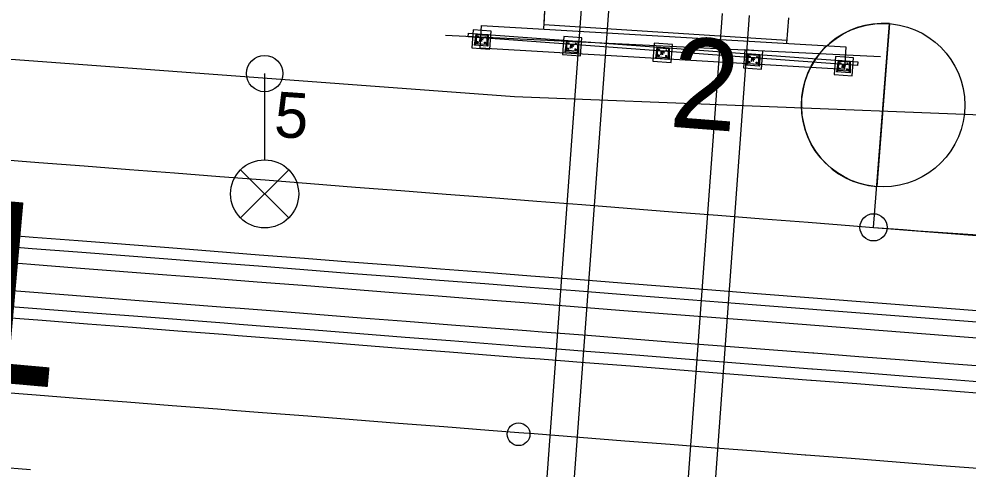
# Model space of a CAD drawing. Extents: x -670359 to -668019, y -978807 to -976674.
# Drawn here: x -669486.95 to -669466.04, y -977146.25 to -977136.34 of the extents above; entities that cross this region are included whole.
import ezdxf

# ---------------------------------------------------------------- set-up
doc = ezdxf.new("R2010")
doc.units = 0
for name, color, linetype in [('SO 01-20-01', 7, 'Continuous'), ('SO 01-20-01_Demolice', 7, 'Continuous'), ('SO 01-86-01', 7, 'Continuous'), ('SO 11-10-01', 7, 'Continuous'), ('SO 11-12-01', 7, 'Continuous'), ('ŽBP', 7, 'Continuous')]:
    doc.layers.add(name, color=color, linetype=linetype)

# ---------------------------------------------------------------- blocks, each defined once
blk = doc.blocks.new('POINT_DISPLAY')
blk.add_line((0, 0), (0, 0))

msp = doc.modelspace()

# ---------------------------------------------------------------- linework, layer by layer
at = {"layer": 'SO 01-20-01'}
for p, q in [((-669475.385, -977136.563), (-669475.124, -977131.902)), ((-669475.38, -977136.467), (-669475.124, -977131.902)), ((-669475.576, -977150.04), (-669474.546, -977136.022)), ((-669474.959, -977149.839), (-669473.947, -977136.066)), ((-669472.47, -977150.083), (-669471.452, -977136.221)), ((-669471.836, -977149.643), (-669470.854, -977136.265)), ((-669469.998, -977136.315), (-669470.039, -977136.876)), ((-669470.034, -977136.814), (-669475.38, -977136.467)), ((-669476.885, -977136.673), (-669476.918, -977136.916)), ((-669476.871, -977136.689), (-669476.886, -977136.889)), ((-669476.615, -977136.693), (-669476.885, -977136.673)), ((-669476.871, -977136.689), (-669476.885, -977136.673)), ((-669476.631, -977136.707), (-669476.871, -977136.689)), ((-669476.854, -977136.731), (-669476.814, -977136.734)), ((-669476.835, -977136.752), (-669476.832, -977136.712)), ((-669476.795, -977136.755), (-669476.801, -977136.835)), ((-669476.716, -977136.761), (-669476.795, -977136.755)), ((-669476.756, -977136.758), (-669476.761, -977136.838)), ((-669476.694, -977136.742), (-669476.654, -977136.745)), ((-669476.676, -977136.764), (-669476.673, -977136.724)), ((-669476.631, -977136.707), (-669476.646, -977136.906)), ((-669476.631, -977136.707), (-669476.615, -977136.693)), ((-669476.615, -977136.693), (-669476.618, -977136.938)), ((-669476.886, -977136.889), (-669476.918, -977136.916)), ((-669476.618, -977136.938), (-669476.918, -977136.916)), ((-669476.646, -977136.906), (-669476.886, -977136.889)), ((-669476.863, -977136.85), (-669476.823, -977136.853)), ((-669476.844, -977136.872), (-669476.841, -977136.832)), ((-669476.719, -977136.801), (-669476.798, -977136.795)), ((-669476.788, -977136.768), (-669476.793, -977136.827)), ((-669476.724, -977136.768), (-669476.783, -977136.764)), ((-669476.703, -977136.862), (-669476.663, -977136.865)), ((-669476.685, -977136.883), (-669476.682, -977136.843)), ((-669476.646, -977136.906), (-669476.618, -977136.938)), ((-669474.89, -977136.82), (-669474.923, -977137.063)), ((-669474.876, -977136.836), (-669474.891, -977137.035)), ((-669474.621, -977136.839), (-669474.89, -977136.82)), ((-669474.876, -977136.836), (-669474.89, -977136.82)), ((-669474.637, -977136.853), (-669474.876, -977136.836)), ((-669474.859, -977136.877), (-669474.819, -977136.88)), ((-669474.841, -977136.899), (-669474.838, -977136.859)), ((-669474.801, -977136.901), (-669474.807, -977136.981)), ((-669474.724, -977136.947), (-669474.804, -977136.941)), ((-669474.721, -977136.907), (-669474.801, -977136.901)), ((-669474.794, -977136.915), (-669474.798, -977136.974)), ((-669474.73, -977136.915), (-669474.788, -977136.91)), ((-669474.761, -977136.904), (-669474.767, -977136.984)), ((-669474.7, -977136.889), (-669474.66, -977136.892)), ((-669474.681, -977136.91), (-669474.678, -977136.87)), ((-669474.637, -977136.853), (-669474.652, -977137.053)), ((-669474.637, -977136.853), (-669474.621, -977136.839)), ((-669474.621, -977136.839), (-669474.624, -977137.085)), ((-669472.895, -977136.966), (-669472.928, -977137.209)), ((-669472.626, -977136.986), (-669472.895, -977136.966)), ((-669472.882, -977136.982), (-669472.895, -977136.966)), ((-669474.891, -977137.035), (-669474.923, -977137.063)), ((-669474.624, -977137.085), (-669474.923, -977137.063)), ((-669474.652, -977137.053), (-669474.891, -977137.035)), ((-669474.868, -977136.997), (-669474.828, -977137)), ((-669474.85, -977137.018), (-669474.847, -977136.978)), ((-669474.708, -977137.009), (-669474.669, -977137.011)), ((-669474.69, -977137.03), (-669474.687, -977136.99)), ((-669474.652, -977137.053), (-669474.624, -977137.085)), ((-669472.882, -977136.982), (-669472.896, -977137.182)), ((-669472.642, -977137), (-669472.882, -977136.982)), ((-669472.873, -977137.143), (-669472.833, -977137.146)), ((-669472.865, -977137.024), (-669472.825, -977137.027)), ((-669472.855, -977137.165), (-669472.852, -977137.125)), ((-669472.846, -977137.045), (-669472.843, -977137.005)), ((-669472.806, -977137.048), (-669472.812, -977137.128)), ((-669472.729, -977137.094), (-669472.809, -977137.088)), ((-669472.726, -977137.054), (-669472.806, -977137.048)), ((-669472.799, -977137.062), (-669472.804, -977137.12)), ((-669472.735, -977137.061), (-669472.794, -977137.057)), ((-669472.766, -977137.051), (-669472.772, -977137.131)), ((-669472.714, -977137.155), (-669472.674, -977137.158)), ((-669472.705, -977137.035), (-669472.665, -977137.038)), ((-669472.695, -977137.176), (-669472.692, -977137.137)), ((-669472.687, -977137.057), (-669472.684, -977137.017)), ((-669472.642, -977137), (-669472.657, -977137.199)), ((-669472.642, -977137), (-669472.626, -977136.986)), ((-669472.626, -977136.986), (-669472.629, -977137.231)), ((-669470.901, -977137.113), (-669470.934, -977137.356)), ((-669470.887, -977137.129), (-669470.902, -977137.328)), ((-669470.632, -977137.133), (-669470.901, -977137.113)), ((-669470.887, -977137.129), (-669470.901, -977137.113)), ((-669470.648, -977137.146), (-669470.887, -977137.129)), ((-669470.87, -977137.17), (-669470.83, -977137.173)), ((-669470.851, -977137.192), (-669470.849, -977137.152)), ((-669470.692, -977137.203), (-669470.689, -977137.163)), ((-669470.648, -977137.146), (-669470.662, -977137.346)), ((-669470.648, -977137.146), (-669470.632, -977137.133)), ((-669470.632, -977137.133), (-669470.635, -977137.378)), ((-669472.896, -977137.182), (-669472.928, -977137.209)), ((-669472.629, -977137.231), (-669472.928, -977137.209)), ((-669472.657, -977137.199), (-669472.896, -977137.182)), ((-669472.657, -977137.199), (-669472.629, -977137.231)), ((-669470.902, -977137.328), (-669470.934, -977137.356)), ((-669470.635, -977137.378), (-669470.934, -977137.356)), ((-669470.662, -977137.346), (-669470.902, -977137.328)), ((-669470.879, -977137.29), (-669470.839, -977137.293)), ((-669470.86, -977137.311), (-669470.857, -977137.271)), ((-669470.812, -977137.195), (-669470.817, -977137.274)), ((-669470.735, -977137.24), (-669470.815, -977137.234)), ((-669470.732, -977137.2), (-669470.812, -977137.195)), ((-669470.805, -977137.208), (-669470.809, -977137.267)), ((-669470.74, -977137.208), (-669470.799, -977137.203)), ((-669470.772, -977137.197), (-669470.778, -977137.277)), ((-669470.719, -977137.302), (-669470.679, -977137.305)), ((-669470.71, -977137.182), (-669470.67, -977137.185)), ((-669470.701, -977137.323), (-669470.698, -977137.283)), ((-669470.662, -977137.346), (-669470.635, -977137.378)), ((-669468.906, -977137.259), (-669468.939, -977137.503)), ((-669468.892, -977137.275), (-669468.907, -977137.475)), ((-669468.637, -977137.279), (-669468.906, -977137.259)), ((-669468.892, -977137.275), (-669468.906, -977137.259)), ((-669468.653, -977137.293), (-669468.892, -977137.275)), ((-669468.875, -977137.317), (-669468.835, -977137.32)), ((-669468.857, -977137.338), (-669468.854, -977137.298)), ((-669468.817, -977137.341), (-669468.823, -977137.421)), ((-669468.74, -977137.387), (-669468.82, -977137.381)), ((-669468.737, -977137.347), (-669468.817, -977137.341)), ((-669468.81, -977137.355), (-669468.814, -977137.413)), ((-669468.746, -977137.354), (-669468.805, -977137.35)), ((-669468.777, -977137.344), (-669468.783, -977137.424)), ((-669468.716, -977137.328), (-669468.676, -977137.331)), ((-669468.697, -977137.35), (-669468.694, -977137.31)), ((-669468.653, -977137.293), (-669468.668, -977137.492)), ((-669468.653, -977137.293), (-669468.637, -977137.279)), ((-669468.637, -977137.279), (-669468.64, -977137.525)), ((-669468.907, -977137.475), (-669468.939, -977137.503)), ((-669468.64, -977137.525), (-669468.939, -977137.503)), ((-669468.668, -977137.492), (-669468.907, -977137.475)), ((-669468.884, -977137.436), (-669468.844, -977137.439)), ((-669468.866, -977137.458), (-669468.863, -977137.418)), ((-669468.725, -977137.448), (-669468.685, -977137.451)), ((-669468.706, -977137.47), (-669468.703, -977137.43)), ((-669468.668, -977137.492), (-669468.64, -977137.525))]:
    msp.add_line(p, q, dxfattribs=at)
for points in [[(-669477.049, -977136.656), (-669468.472, -977137.286), (-669468.478, -977137.366), (-669477.055, -977136.736)], [(-669476.544, -977136.611), (-669476.943, -977136.581), (-669476.972, -977136.98), (-669476.574, -977137.01)], [(-669474.55, -977136.757), (-669474.949, -977136.728), (-669474.978, -977137.127), (-669474.579, -977137.156)], [(-669472.555, -977136.904), (-669472.954, -977136.874), (-669472.983, -977137.273), (-669472.584, -977137.303)], [(-669470.56, -977137.05), (-669470.959, -977137.021), (-669470.989, -977137.42), (-669470.59, -977137.449)], [(-669468.566, -977137.197), (-669468.965, -977137.168), (-669468.994, -977137.566), (-669468.595, -977137.596)]]:
    msp.add_lwpolyline(points, close=True, dxfattribs=at)
for centre in [(-669476.834, -977136.732), (-669476.674, -977136.744), (-669476.843, -977136.852), (-669476.683, -977136.863), (-669474.839, -977136.879), (-669474.68, -977136.89), (-669474.848, -977136.998), (-669474.688, -977137.01), (-669472.853, -977137.145), (-669472.845, -977137.025), (-669472.694, -977137.157), (-669472.685, -977137.037), (-669470.85, -977137.172), (-669470.69, -977137.183), (-669470.859, -977137.291), (-669470.699, -977137.303), (-669468.855, -977137.318), (-669468.696, -977137.33), (-669468.864, -977137.438), (-669468.705, -977137.45)]:
    msp.add_circle(centre, 0.01, dxfattribs=at)
for centre, radius, start, end in [((-669476.801, -977136.827), 0.008, 265.7861, 355.7984), ((-669476.783, -977136.769), 0.005, 85.7984, 175.7984), ((-669476.724, -977136.76), 0.008, 265.7861, 355.7984), ((-669474.789, -977136.915), 0.005, 85.7984, 175.7984), ((-669474.729, -977136.907), 0.008, 265.7861, 355.7984), ((-669474.806, -977136.973), 0.008, 265.7861, 355.7984), ((-669472.811, -977137.12), 0.008, 265.7861, 355.7984), ((-669472.794, -977137.062), 0.005, 85.7984, 175.7984), ((-669472.734, -977137.053), 0.008, 265.7861, 355.7984), ((-669470.817, -977137.266), 0.008, 265.7861, 355.7984), ((-669470.8, -977137.208), 0.005, 85.7984, 175.7984), ((-669470.74, -977137.2), 0.008, 265.7861, 355.7984), ((-669468.805, -977137.355), 0.005, 85.7984, 175.7984), ((-669468.745, -977137.346), 0.008, 265.7861, 355.7984), ((-669468.822, -977137.413), 0.008, 265.7861, 355.7984)]:
    msp.add_arc(centre, radius, start, end, dxfattribs=at)
at = {"layer": 'SO 01-20-01_Demolice'}
for p, q in [((-669476.785, -977136.981), (-669476.756, -977136.482)), ((-669476.756, -977136.482), (-669468.736, -977136.955)), ((-669477.549, -977136.696), (-669467.971, -977137.168)), ((-669468.736, -977136.955), (-669468.765, -977137.454)), ((-669468.765, -977137.454), (-669476.785, -977136.981))]:
    msp.add_line(p, q, dxfattribs=at)
at = {"layer": 'SO 01-86-01'}
for p, q in [((-669492.657, -977136.821), (-669476.036, -977138.048)), ((-669481.536, -977137.544), (-669481.536, -977139.044)), ((-669481.536, -977137.944), (-669481.536, -977139.444)), ((-669476.036, -977138.048), (-669457.361, -977138.783)), ((-669482.067, -977139.664), (-669481.006, -977140.724)), ((-669481.006, -977139.664), (-669482.067, -977140.724)), ((-669481.536, -977140.944), (-669481.536, -977140.944))]:
    msp.add_line(p, q, dxfattribs=at)
for centre, radius in [((-669481.536, -977137.544), 0.4), ((-669481.536, -977140.194), 0.75)]:
    msp.add_circle(centre, radius, dxfattribs=at)
at = {"layer": 'SO 11-10-01'}
for p, q in [((-669468.123, -977140.931), (-669467.774, -977136.444)), ((-669487.506, -977139.422), (-669486.509, -977139.5)), ((-669486.509, -977139.5), (-669485.512, -977139.577)), ((-669485.512, -977139.577), (-669484.515, -977139.655)), ((-669484.515, -977139.655), (-669483.518, -977139.732)), ((-669483.518, -977139.732), (-669482.521, -977139.81)), ((-669482.521, -977139.81), (-669481.525, -977139.888)), ((-669481.525, -977139.888), (-669480.528, -977139.965)), ((-669480.528, -977139.965), (-669479.531, -977140.043)), ((-669479.531, -977140.043), (-669478.534, -977140.12)), ((-669478.534, -977140.12), (-669477.537, -977140.198)), ((-669477.537, -977140.198), (-669476.54, -977140.276)), ((-669476.54, -977140.276), (-669475.543, -977140.353)), ((-669475.543, -977140.353), (-669474.546, -977140.431)), ((-669474.546, -977140.431), (-669473.549, -977140.508)), ((-669473.549, -977140.508), (-669472.552, -977140.586)), ((-669472.552, -977140.586), (-669471.555, -977140.664)), ((-669471.555, -977140.664), (-669470.558, -977140.741)), ((-669470.558, -977140.741), (-669469.561, -977140.819)), ((-669469.561, -977140.819), (-669468.564, -977140.896)), ((-669468.564, -977140.896), (-669468.123, -977140.931)), ((-669468.123, -977140.931), (-669441.067, -977143.037)), ((-669487.562, -977144.543), (-669486.565, -977144.621)), ((-669486.565, -977144.621), (-669485.568, -977144.698)), ((-669485.568, -977144.698), (-669484.571, -977144.776)), ((-669484.571, -977144.776), (-669483.574, -977144.853)), ((-669483.574, -977144.853), (-669482.577, -977144.931)), ((-669482.577, -977144.931), (-669482.246, -977144.957)), ((-669482.246, -977144.957), (-669481.58, -977145.009)), ((-669481.58, -977145.009), (-669480.583, -977145.086)), ((-669480.583, -977145.086), (-669479.586, -977145.164)), ((-669479.586, -977145.164), (-669478.589, -977145.241)), ((-669478.589, -977145.241), (-669477.592, -977145.319)), ((-669477.592, -977145.319), (-669476.595, -977145.397)), ((-669476.595, -977145.397), (-669475.939, -977145.448)), ((-669475.939, -977145.448), (-669475.598, -977145.474)), ((-669475.598, -977145.474), (-669474.601, -977145.552)), ((-669474.601, -977145.552), (-669473.604, -977145.63)), ((-669473.604, -977145.63), (-669472.607, -977145.707)), ((-669472.607, -977145.707), (-669471.61, -977145.785)), ((-669471.61, -977145.785), (-669470.613, -977145.862)), ((-669470.613, -977145.862), (-669469.632, -977145.939)), ((-669469.632, -977145.939), (-669469.616, -977145.94)), ((-669469.616, -977145.94), (-669468.619, -977146.018)), ((-669468.619, -977146.018), (-669467.622, -977146.095)), ((-669467.622, -977146.095), (-669466.625, -977146.173)), ((-669466.625, -977146.173), (-669465.628, -977146.25))]:
    msp.add_line(p, q, dxfattribs=at)
msp.add_lwpolyline([(-669467.774, -977136.444), (-669468.053, -977140.033), (-669468.053, -977140.033)], dxfattribs=at)
for centre, radius in [((-669467.914, -977138.239), 1.8), ((-669468.123, -977140.931), 0.3), ((-669475.942, -977145.488), 0.25)]:
    msp.add_circle(centre, radius, dxfattribs=at)
for centre, radius, start, end in [((-669467.914, -977138.239), 1.8, 85.5493, 265.5478), ((-669453.379, -976951.504), 190, 265.54926, 271.88929)]:
    msp.add_arc(centre, radius, start, end, dxfattribs=at)
at = {"layer": 'SO 11-12-01'}
for p, q in [((-669487.634, -977141.067), (-669486.637, -977141.145)), ((-669486.637, -977141.145), (-669485.64, -977141.222)), ((-669487.654, -977141.316), (-669486.657, -977141.394)), ((-669485.64, -977141.222), (-669483.647, -977141.377)), ((-669486.657, -977141.394), (-669485.66, -977141.471)), ((-669485.66, -977141.471), (-669483.666, -977141.627)), ((-669483.647, -977141.377), (-669482.65, -977141.455)), ((-669482.65, -977141.455), (-669481.653, -977141.533)), ((-669481.653, -977141.533), (-669480.656, -977141.61)), ((-669487.681, -977141.665), (-669486.684, -977141.743)), ((-669486.684, -977141.743), (-669485.687, -977141.82)), ((-669483.666, -977141.627), (-669482.669, -977141.704)), ((-669482.669, -977141.704), (-669481.672, -977141.782)), ((-669480.656, -977141.61), (-669479.659, -977141.688)), ((-669479.659, -977141.688), (-669478.662, -977141.765)), ((-669478.662, -977141.765), (-669477.665, -977141.843)), ((-669485.687, -977141.82), (-669483.693, -977141.976)), ((-669483.693, -977141.976), (-669482.696, -977142.053)), ((-669481.672, -977141.782), (-669480.675, -977141.859)), ((-669480.675, -977141.859), (-669479.678, -977141.937)), ((-669479.678, -977141.937), (-669478.681, -977142.015)), ((-669477.665, -977141.843), (-669476.668, -977141.921)), ((-669476.668, -977141.921), (-669475.671, -977141.998)), ((-669482.696, -977142.053), (-669481.699, -977142.131)), ((-669481.699, -977142.131), (-669480.702, -977142.208)), ((-669478.681, -977142.015), (-669477.684, -977142.092)), ((-669477.684, -977142.092), (-669476.687, -977142.17)), ((-669476.687, -977142.17), (-669475.69, -977142.247)), ((-669475.671, -977141.998), (-669474.674, -977142.076)), ((-669474.674, -977142.076), (-669473.677, -977142.153)), ((-669473.677, -977142.153), (-669471.683, -977142.309)), ((-669487.387, -977142.3), (-669485.394, -977142.455)), ((-669480.702, -977142.208), (-669479.705, -977142.286)), ((-669479.705, -977142.286), (-669478.708, -977142.364)), ((-669478.708, -977142.364), (-669477.711, -977142.441)), ((-669475.69, -977142.247), (-669474.693, -977142.325)), ((-669474.693, -977142.325), (-669473.696, -977142.403)), ((-669473.696, -977142.403), (-669470.705, -977142.635)), ((-669471.683, -977142.309), (-669470.686, -977142.386)), ((-669470.686, -977142.386), (-669440.359, -977144.747)), ((-669485.394, -977142.455), (-669484.397, -977142.533)), ((-669484.397, -977142.533), (-669482.403, -977142.688)), ((-669477.711, -977142.441), (-669476.714, -977142.519)), ((-669476.714, -977142.519), (-669475.717, -977142.596)), ((-669475.717, -977142.596), (-669474.72, -977142.674)), ((-669487.415, -977142.649), (-669485.421, -977142.804)), ((-669485.421, -977142.804), (-669484.424, -977142.882)), ((-669482.403, -977142.688), (-669482.072, -977142.714)), ((-669482.072, -977142.714), (-669481.406, -977142.765)), ((-669481.406, -977142.765), (-669480.409, -977142.843)), ((-669474.72, -977142.674), (-669473.723, -977142.752)), ((-669473.723, -977142.752), (-669470.732, -977142.984)), ((-669470.705, -977142.635), (-669440.379, -977144.996)), ((-669487.434, -977142.898), (-669486.437, -977142.976)), ((-669486.437, -977142.976), (-669485.44, -977143.053)), ((-669484.424, -977142.882), (-669482.43, -977143.037)), ((-669480.409, -977142.843), (-669479.412, -977142.921)), ((-669479.412, -977142.921), (-669478.415, -977142.998)), ((-669478.415, -977142.998), (-669477.418, -977143.076)), ((-669470.732, -977142.984), (-669440.406, -977145.345)), ((-669485.44, -977143.053), (-669484.443, -977143.131)), ((-669484.443, -977143.131), (-669483.446, -977143.208)), ((-669483.446, -977143.208), (-669482.449, -977143.286)), ((-669482.43, -977143.037), (-669482.099, -977143.063)), ((-669482.099, -977143.063), (-669481.433, -977143.114)), ((-669481.433, -977143.114), (-669480.436, -977143.192)), ((-669480.436, -977143.192), (-669479.439, -977143.27)), ((-669477.418, -977143.076), (-669475.765, -977143.205)), ((-669475.765, -977143.205), (-669475.424, -977143.231)), ((-669475.424, -977143.231), (-669474.427, -977143.309)), ((-669482.449, -977143.286), (-669482.118, -977143.312)), ((-669482.118, -977143.312), (-669481.452, -977143.364)), ((-669481.452, -977143.364), (-669480.455, -977143.441)), ((-669480.455, -977143.441), (-669479.458, -977143.519)), ((-669479.439, -977143.27), (-669478.442, -977143.347)), ((-669478.442, -977143.347), (-669477.445, -977143.425)), ((-669477.445, -977143.425), (-669475.792, -977143.554)), ((-669474.427, -977143.309), (-669473.43, -977143.386)), ((-669473.43, -977143.386), (-669472.433, -977143.464)), ((-669479.458, -977143.519), (-669478.461, -977143.596)), ((-669478.461, -977143.596), (-669477.464, -977143.674)), ((-669475.792, -977143.554), (-669475.451, -977143.58)), ((-669475.451, -977143.58), (-669474.454, -977143.658)), ((-669474.454, -977143.658), (-669473.457, -977143.735)), ((-669472.433, -977143.464), (-669469.458, -977143.696)), ((-669477.464, -977143.674), (-669476.467, -977143.752)), ((-669476.467, -977143.752), (-669475.811, -977143.803)), ((-669475.811, -977143.803), (-669475.47, -977143.829)), ((-669475.47, -977143.829), (-669474.473, -977143.907)), ((-669473.457, -977143.735), (-669472.46, -977143.813)), ((-669472.46, -977143.813), (-669469.485, -977144.044)), ((-669469.458, -977143.696), (-669469.442, -977143.697)), ((-669469.442, -977143.697), (-669468.445, -977143.774)), ((-669468.445, -977143.774), (-669467.448, -977143.852)), ((-669467.448, -977143.852), (-669466.451, -977143.93)), ((-669474.473, -977143.907), (-669473.476, -977143.985)), ((-669473.476, -977143.985), (-669472.479, -977144.062)), ((-669472.479, -977144.062), (-669471.482, -977144.14)), ((-669469.485, -977144.044), (-669469.469, -977144.046)), ((-669469.469, -977144.046), (-669468.472, -977144.123)), ((-669466.451, -977143.93), (-669465.454, -977144.007)), ((-669471.482, -977144.14), (-669469.504, -977144.294)), ((-669468.472, -977144.123), (-669467.475, -977144.201)), ((-669467.475, -977144.201), (-669466.478, -977144.278)), ((-669466.478, -977144.278), (-669465.481, -977144.356)), ((-669469.504, -977144.294), (-669469.488, -977144.295)), ((-669469.488, -977144.295), (-669468.491, -977144.373)), ((-669468.491, -977144.373), (-669467.494, -977144.45)), ((-669467.494, -977144.45), (-669466.497, -977144.528)), ((-669466.497, -977144.528), (-669465.5, -977144.605)), ((-669487.69, -977146.188), (-669486.693, -977146.266))]:
    msp.add_line(p, q, dxfattribs=at)

# ---------------------------------------------------------------- block references
at = {"layer": 'SO 01-86-01', "rotation": 4.450857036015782}
msp.add_blockref('POINT_DISPLAY', (-669481.566, -977137.56), dxfattribs=at)
at = {"layer": 'SO 11-10-01'}
msp.add_blockref('POINT_DISPLAY', (-669468.123, -977140.931), dxfattribs=at)
msp.add_blockref('POINT_DISPLAY', (-669468.123, -977140.931), dxfattribs=at)

# ---------------------------------------------------------------- texts
at = {"layer": 'SO 01-86-01'}
msp.add_text('5', height=1, rotation=356.1, dxfattribs=at).set_placement((-669481.345, -977138.934))
at = {"layer": 'SO 11-10-01'}
msp.add_text('2', height=2, rotation=355.5464, dxfattribs=at).set_placement((-669472.649, -977138.71))
at = {"layer": 'ŽBP'}
msp.add_text('2001', height=3.9996, rotation=354.8935, dxfattribs=at).set_placement((-669497.904, -977143.413))

doc.saveas('drawing.dxf')
